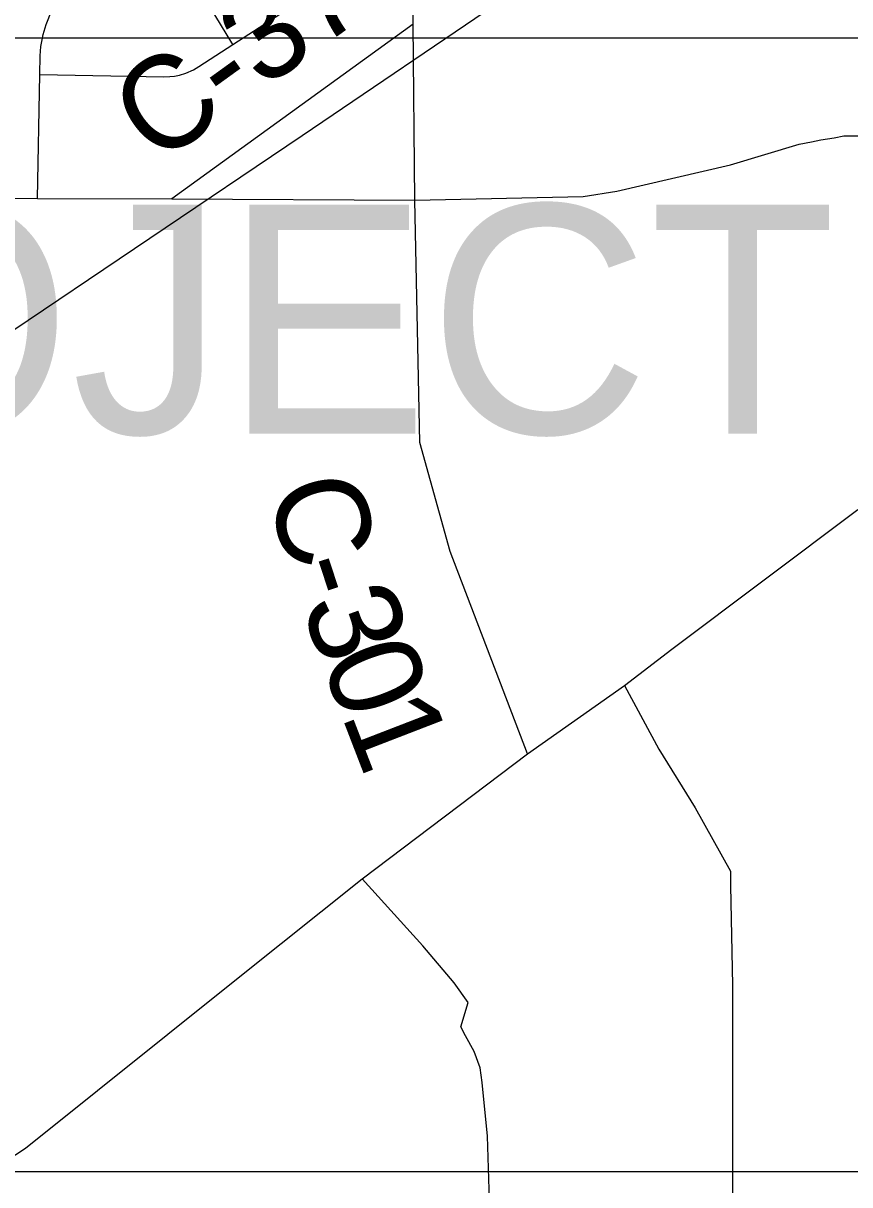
# Model space of a CAD drawing. Extents: x -59 to 82, y -3 to 49.
# Drawn here: x -51.082 to -50.577, y 45.726 to 46.436 of the extents above; entities that cross this region are included whole.
import ezdxf

# ---------------------------------------------------------------- set-up
doc = ezdxf.new("R2010")
doc.units = 0
for name, color, linetype in [('GM_X_County_Road', 7, 'Continuous'), ('GM_X_County_Road_Text', 7, 'Continuous'), ('GM_X_Rail_Line', 7, 'Continuous'), ('GM_X_State_Route', 7, 'Continuous'), ('GM_X_Township_Road', 7, 'Continuous'), ('SH_Data', 7, 'Continuous')]:
    doc.layers.add(name, color=color, linetype=linetype)

msp = doc.modelspace()

# ---------------------------------------------------------------- linework, layer by layer
at = {"layer": 'GM_X_County_Road'}
for p, q in [((-50.84363, 46.43544), (-50.84518, 46.62042)), ((-50.84363, 46.43544), (-50.99152, 46.32868)), ((-50.84273, 46.32778), (-50.84363, 46.43544)), ((-50.59988, 46.36358), (-50.59417, 46.36466)), ((-50.59417, 46.36466), (-50.5861, 46.36602)), ((-50.5861, 46.36602), (-50.58018, 46.36709)), ((-50.58018, 46.36709), (-50.56725, 46.36715)), ((-50.64951, 46.34953), (-50.60749, 46.36215)), ((-50.60749, 46.36215), (-50.59988, 46.36358)), ((-50.71907, 46.33335), (-50.64951, 46.34953)), ((-51.38874, 46.33189), (-51.07358, 46.32889)), ((-50.84273, 46.32778), (-50.73958, 46.33011)), ((-50.73958, 46.33011), (-50.71907, 46.33335)), ((-51.07358, 46.32889), (-50.99152, 46.32868)), ((-50.99152, 46.32868), (-50.84273, 46.32778)), ((-50.83964, 46.17966), (-50.84273, 46.32778)), ((-50.82106, 46.11298), (-50.83964, 46.17966)), ((-50.77367, 45.98907), (-50.82106, 46.11298))]:
    msp.add_line(p, q, dxfattribs=at)
at = {"layer": 'GM_X_Rail_Line'}
for p, q in [((-50.91171, 46.36748), (-50.63229, 46.55662)), ((-51.23431, 46.15016), (-50.91171, 46.36748))]:
    msp.add_line(p, q, dxfattribs=at)
at = {"layer": 'GM_X_State_Route'}
for p, q in [((-50.68533, 46.05324), (-50.57158, 46.13855)), ((-50.71446, 46.03093), (-50.68533, 46.05324)), ((-50.77367, 45.98907), (-50.71446, 46.03093)), ((-50.87496, 45.91272), (-50.77367, 45.98907)), ((-50.94979, 45.85286), (-50.87496, 45.91272)), ((-51.08096, 45.74788), (-50.94979, 45.85286)), ((-51.11513, 45.72586), (-51.08096, 45.74788))]:
    msp.add_line(p, q, dxfattribs=at)
at = {"layer": 'GM_X_Township_Road'}
for p, q in [((-51.06828, 46.4353), (-51.06101, 46.45422)), ((-50.954, 46.42308), (-50.96852, 46.44692)), ((-50.954, 46.42308), (-50.92178, 46.44396)), ((-51.07089, 46.42594), (-51.07025, 46.42912)), ((-51.07025, 46.42912), (-51.06828, 46.4353)), ((-51.07201, 46.41605), (-51.0716, 46.42193)), ((-51.0716, 46.42193), (-51.07089, 46.42594)), ((-50.9749, 46.40953), (-50.954, 46.42308)), ((-51.07222, 46.40468), (-51.07201, 46.41605)), ((-50.98281, 46.40556), (-50.97825, 46.40756)), ((-50.97825, 46.40756), (-50.9749, 46.40953)), ((-51.07358, 46.32889), (-51.07222, 46.40468)), ((-51.07222, 46.40468), (-50.99642, 46.4033)), ((-50.99642, 46.4033), (-50.99257, 46.40342)), ((-50.99257, 46.40342), (-50.98974, 46.40377)), ((-50.98974, 46.40377), (-50.9868, 46.40436)), ((-50.9868, 46.40436), (-50.98281, 46.40556)), ((-50.71446, 46.03093), (-50.69345, 45.99206)), ((-50.69345, 45.99206), (-50.67118, 45.95609)), ((-50.67118, 45.95609), (-50.64957, 45.91743)), ((-50.64957, 45.91743), (-50.64943, 45.90934)), ((-50.83787, 45.87173), (-50.87496, 45.91272)), ((-50.64943, 45.90934), (-50.64941, 45.90834)), ((-50.64941, 45.90834), (-50.64834, 45.84761)), ((-50.81857, 45.84896), (-50.83787, 45.87173)), ((-50.8101, 45.83703), (-50.81857, 45.84896)), ((-50.64834, 45.84761), (-50.64811, 45.57857)), ((-50.8145, 45.82221), (-50.8101, 45.83703)), ((-50.8116, 45.81656), (-50.8145, 45.82221)), ((-50.80636, 45.80711), (-50.8116, 45.81656)), ((-50.80269, 45.79714), (-50.80636, 45.80711)), ((-50.80142, 45.78816), (-50.80269, 45.79714)), ((-50.79822, 45.75525), (-50.80142, 45.78816)), ((-50.78921, 45.46774), (-50.79822, 45.75525))]:
    msp.add_line(p, q, dxfattribs=at)
at = {"layer": 'SH_Data'}
msp.add_lwpolyline([(-52.16577, 45.73353), (-50.40823, 45.73353), (-50.40823, 46.42698), (-52.16577, 46.42698)], close=True, dxfattribs=at)
msp.add_lwpolyline([(-52.16577, 45.73353), (-50.40823, 45.73353), (-50.40823, 46.42698), (-52.16577, 46.42698)], close=True, dxfattribs=at)

# ---------------------------------------------------------------- texts
at = {"layer": 'GM_X_County_Road_Text'}
for s, height, rotation, p in [('C-379', 0.056818, 35.82675, (-51.00074, 46.34825)), ('C', 0.05682, 286.16467, (-50.93399, 46.151)), ('-', 0.05682, 288.18092, (-50.92035, 46.10409)), ('3', 0.05682, 289.44589, (-50.91263, 46.08062)), ('0', 0.05682, 290.7471, (-50.90049, 46.0463)), ('1', 0.05682, 291.10739, (-50.88796, 46.0132))]:
    msp.add_text(s, height=height, rotation=rotation, dxfattribs=at).set_placement(p)
at = {"layer": 'SH_Data'}
msp.add_text('BEGIN PROJECT', height=0.14, dxfattribs=at).set_placement((-52.09313, 46.18503))

doc.saveas('drawing.dxf')
